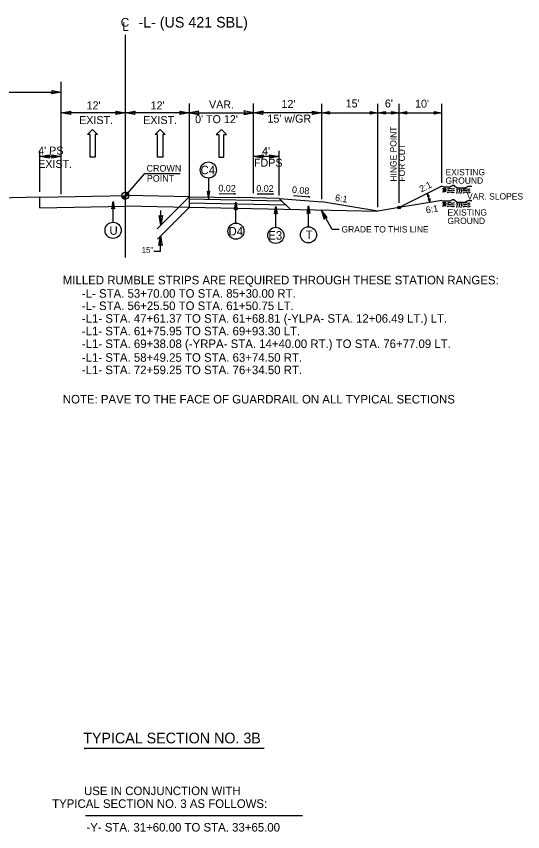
# Model space of a CAD drawing. Extents: x 573813 to 575363, y -54752 to -53123.
# Drawn here: x 574446.6 to 574554.5, y -53538.7 to -53364.9 of the extents above; entities that cross this region are included whole.
import ezdxf

# ---------------------------------------------------------------- set-up
doc = ezdxf.new("R2010")
doc.units = 0
for name, color, linetype in [('Old_Level_1', 7, 'Continuous'), ('Old_Level_11', 7, 'Continuous'), ('Old_Level_2', 7, 'Continuous'), ('Old_Level_3', 7, 'Continuous'), ('Old_Level_4', 7, 'Continuous'), ('Prop Pavement Schedule Description CELL', 7, 'Continuous'), ('Typical Grade Point Symbol CELL', 7, 'Continuous'), ('Typical ID Circle CELL', 7, 'Continuous'), ('Typical Pavement Slope CELL', 7, 'Continuous'), ('Typical Terminator CELL', 7, 'Continuous'), ('Typical Text ID Circle CELL', 7, 'Continuous')]:
    doc.layers.add(name, color=color, linetype=linetype)

msp = doc.modelspace()

# ---------------------------------------------------------------- linework, layer by layer
at = {"layer": 'Old_Level_1'}
for p, q in [((574493, -53402.58), (574493.38, -53402.77)), ((574537.31, -53401.09), (574528.21, -53405.64)), ((574451.69, -53403.42), (574442.59, -53403.61)), ((574451.69, -53403.42), (574470.39, -53403.1)), ((574451.69, -53405.68), (574451.69, -53403.42)), ((574483.52, -53403.32), (574470.39, -53403.1)), ((574483.52, -53405.56), (574483.52, -53403.29)), ((574483.52, -53403.32), (574494.22, -53403.51)), ((574503.26, -53404.29), (574483.52, -53403.88)), ((574493.38, -53402.77), (574489.87, -53402.7)), ((574502.65, -53403.68), (574494.22, -53403.51)), ((574501.46, -53402.82), (574497.95, -53402.75)), ((574501.08, -53402.63), (574501.46, -53402.82)), ((574502.65, -53403.68), (574511.75, -53404.41)), ((574502.65, -53403.68), (574504.98, -53406.01)), ((574509.22, -53403.41), (574505.72, -53403.11)), ((574508.85, -53403.2), (574509.22, -53403.41)), ((574537.31, -53404.12), (574528.21, -53405.64)), ((574451.69, -53405.68), (574469.88, -53405.36)), ((574483.49, -53405.6), (574469.88, -53405.36)), ((574483.52, -53404.64), (574504.04, -53405.07)), ((574483.52, -53405.56), (574523.67, -53406.4)), ((574523.67, -53406.4), (574511.75, -53404.41)), ((574528.21, -53405.64), (574523.67, -53406.4))]:
    msp.add_line(p, q, dxfattribs=at)
for points in [[(574537.31, -53401.09), (574538.2, -53401.2), (574538.43, -53401.2), (574538.76, -53401.2), (574538.99, -53401.2), (574539.21, -53401.09), (574539.44, -53400.98), (574539.66, -53400.87), (574539.88, -53400.87), (574540, -53401.09), (574540.22, -53401.2), (574540.44, -53401.32), (574540.67, -53401.43), (574540.89, -53401.43), (574541.12, -53401.43), (574541.34, -53401.43), (574541.56, -53401.43), (574541.79, -53401.43), (574542.01, -53401.43), (574542.24, -53401.43), (574542.46, -53401.32), (574542.69, -53401.2), (574542.91, -53401.09), (574543.25, -53401.09), (574543.47, -53401.09), (574543.69, -53401.09)], [(574537.31, -53404.12), (574538.2, -53404.23), (574538.43, -53404.23), (574538.76, -53404.23), (574538.99, -53404.23), (574539.21, -53404.12), (574539.44, -53404.01), (574539.66, -53403.9), (574539.88, -53403.9), (574540, -53404.12), (574540.22, -53404.23), (574540.44, -53404.35), (574540.67, -53404.46), (574540.89, -53404.46), (574541.12, -53404.46), (574541.34, -53404.46), (574541.56, -53404.46), (574541.79, -53404.46), (574542.01, -53404.46), (574542.24, -53404.46), (574542.46, -53404.35), (574542.69, -53404.23), (574542.91, -53404.12), (574543.25, -53404.12), (574543.47, -53404.12), (574543.69, -53404.12)]]:
    msp.add_lwpolyline(points, dxfattribs=at)
msp.add_circle((574528.21, -53405.64), 0.27, dxfattribs=at)
msp.add_arc((574527.83, -53405.75), 7.04, 9.8122, 26.0666, dxfattribs=at)
at = {"layer": 'Old_Level_11'}
for p, q in [((574456.24, -53401.29), (574456.24, -53378.84)), ((574372.1, -53381.02), (574456.24, -53381.02)), ((574483.52, -53400.65), (574483.53, -53383.48)), ((574497.16, -53402.6), (574497.16, -53383.48)), ((574511.75, -53403.84), (574511.75, -53383.55)), ((574523.69, -53405.57), (574523.69, -53383.55)), ((574528.21, -53404.65), (574528.21, -53383.55)), ((574537.31, -53400.38), (574537.31, -53383.55)), ((574469.88, -53385.43), (574456.24, -53385.43)), ((574483.53, -53385.43), (574469.88, -53385.43)), ((574483.52, -53385.42), (574497.16, -53385.42)), ((574511.75, -53385.42), (574497.16, -53385.42)), ((574511.75, -53385.42), (574522.8, -53385.42)), ((574522.8, -53385.42), (574528.25, -53385.42)), ((574528.25, -53385.42), (574537.35, -53385.42)), ((574456.24, -53402.76), (574456.24, -53387.72)), ((574451.69, -53402.3), (574451.69, -53393.57)), ((574483.52, -53403.21), (574483.52, -53392.7)), ((574483.52, -53402.87), (574483.52, -53392.81)), ((574502.67, -53403.05), (574502.67, -53393.57)), ((574456.24, -53394.76), (574451.69, -53394.76)), ((574502.67, -53394.74), (574497.16, -53394.74)), ((574456.24, -53402.76), (574456.24, -53396.25)), ((574469.88, -53403.11), (574474.05, -53398.38)), ((574474.05, -53398.38), (574481.55, -53398.38)), ((574483.52, -53403.29), (574476.65, -53410.16)), ((574483.52, -53405.56), (574476.72, -53412.37)), ((574477.42, -53409.37), (574477.42, -53406.29)), ((574513.93, -53410.33), (574511.6, -53406.14)), ((574515.44, -53410.33), (574513.93, -53410.33)), ((574477.38, -53414.91), (574477.38, -53411.7)), ((574475.92, -53414.91), (574477.38, -53414.91)), ((574499.46, -53520.94), (574461.09, -53520.94)), ((574461.39, -53535.24), (574507.63, -53535.24))]:
    msp.add_line(p, q, dxfattribs=at)
for points in [[(574454.19, -53380.67), (574456.24, -53381.02), (574454.18, -53381.39), (574454.44, -53381.02)], [(574458.28, -53385.78), (574456.24, -53385.43), (574458.3, -53385.07), (574458.03, -53385.43)], [(574467.83, -53385.08), (574469.88, -53385.43), (574467.82, -53385.8), (574468.08, -53385.43)], [(574471.93, -53385.78), (574469.88, -53385.43), (574471.94, -53385.07), (574471.68, -53385.43)], [(574481.48, -53385.08), (574483.53, -53385.43), (574481.47, -53385.8), (574481.73, -53385.43)], [(574485.57, -53385.07), (574483.52, -53385.42), (574485.58, -53385.78), (574485.32, -53385.42)], [(574495.11, -53385.77), (574497.16, -53385.42), (574495.1, -53385.05), (574495.36, -53385.42)], [(574499.2, -53385.77), (574497.16, -53385.42), (574499.21, -53385.05), (574498.95, -53385.42)], [(574509.7, -53385.07), (574511.75, -53385.42), (574509.69, -53385.78), (574509.95, -53385.42)], [(574513.39, -53385.7), (574511.75, -53385.42), (574513.39, -53385.13), (574513.19, -53385.42)], [(574522.05, -53385.14), (574523.69, -53385.42), (574522.05, -53385.71), (574522.25, -53385.42)], [(574525.33, -53385.7), (574523.69, -53385.42), (574525.34, -53385.13), (574525.13, -53385.42)], [(574526.57, -53385.14), (574528.21, -53385.42), (574526.56, -53385.71), (574526.77, -53385.42)], [(574529.85, -53385.7), (574528.21, -53385.42), (574529.86, -53385.13), (574529.65, -53385.42)], [(574535.67, -53385.14), (574537.31, -53385.42), (574535.66, -53385.71), (574535.87, -53385.42)], [(574453.74, -53395.11), (574451.69, -53394.76), (574453.75, -53394.4), (574453.49, -53394.76)], [(574454.19, -53394.41), (574456.24, -53394.76), (574454.18, -53395.12), (574454.44, -53394.76)], [(574499.2, -53395.1), (574497.16, -53394.74), (574499.21, -53394.38), (574498.95, -53394.74)], [(574500.62, -53394.39), (574502.67, -53394.74), (574500.61, -53395.11), (574500.87, -53394.74)], [(574534.38, -53403.45), (574534.15, -53402.65), (574534.64, -53403.33), (574534.46, -53403.3)], [(574534.76, -53403.72), (574534.76, -53404.55), (574534.48, -53403.76), (574534.64, -53403.84)], [(574477.77, -53407.32), (574477.42, -53409.37), (574477.06, -53407.31), (574477.42, -53407.57)], [(574512.89, -53407.76), (574511.6, -53406.14), (574512.27, -53408.12), (574512.47, -53407.72)], [(574477.03, -53413.75), (574477.38, -53411.7), (574477.75, -53413.76), (574477.38, -53413.5)]]:
    msp.add_lwpolyline(points, close=True, dxfattribs=at)
at = {"layer": 'Old_Level_2'}
for p, q in [((574469.88, -53385.94), (574469.88, -53368.79)), ((574469.88, -53416.28), (574469.88, -53385.94))]:
    msp.add_line(p, q, dxfattribs=at)
for points in [[(574537.46, -53401.41), (574537.62, -53401.86), (574537.45, -53402.46)], [(574537.46, -53401.41), (574537.62, -53401.86), (574537.45, -53402.46)], [(574537.73, -53401.36), (574537.88, -53401.81), (574537.71, -53402.41)], [(574537.73, -53401.36), (574537.88, -53401.81), (574537.71, -53402.41)], [(574538.01, -53401.33), (574538.17, -53401.78), (574538, -53402.38)], [(574538.01, -53401.33), (574538.17, -53401.78), (574538, -53402.38)], [(574538.45, -53402.45), (574539, -53402.29), (574539.58, -53402.44), (574539.99, -53402.35)], [(574538.45, -53402.45), (574539, -53402.29), (574539.58, -53402.44), (574539.99, -53402.35)], [(574538.49, -53401.68), (574539.04, -53401.53), (574539.62, -53401.67), (574540.03, -53401.58)], [(574538.49, -53401.68), (574539.04, -53401.53), (574539.62, -53401.67), (574540.03, -53401.58)], [(574538.49, -53402.06), (574539.04, -53401.91), (574539.62, -53402.06), (574540.03, -53401.96)], [(574538.49, -53402.06), (574539.04, -53401.91), (574539.62, -53402.06), (574540.03, -53401.96)], [(574540.41, -53401.55), (574540.56, -53402.01), (574540.4, -53402.61)], [(574540.41, -53401.55), (574540.56, -53402.01), (574540.4, -53402.61)], [(574540.88, -53401.59), (574541.04, -53402.04), (574540.87, -53402.64)], [(574540.88, -53401.59), (574541.04, -53402.04), (574540.87, -53402.64)], [(574541.33, -53401.63), (574541.48, -53402.08), (574541.31, -53402.68)], [(574541.33, -53401.63), (574541.48, -53402.08), (574541.31, -53402.68)], [(574541.78, -53401.74), (574542.33, -53401.58), (574542.9, -53401.73), (574543.32, -53401.63)], [(574541.78, -53401.74), (574542.33, -53401.58), (574542.9, -53401.73), (574543.32, -53401.63)], [(574541.79, -53402.08), (574542.34, -53401.92), (574542.92, -53402.07), (574543.33, -53401.98)], [(574541.79, -53402.08), (574542.34, -53401.92), (574542.92, -53402.07), (574543.33, -53401.98)], [(574541.85, -53402.48), (574542.4, -53402.32), (574542.97, -53402.47), (574543.39, -53402.37)], [(574541.85, -53402.48), (574542.4, -53402.32), (574542.97, -53402.47), (574543.39, -53402.37)], [(574538.01, -53404.33), (574538.17, -53404.78), (574538, -53405.38)], [(574538.01, -53404.33), (574538.17, -53404.78), (574538, -53405.38)], [(574537.46, -53404.41), (574537.62, -53404.86), (574537.45, -53405.46)], [(574537.46, -53404.41), (574537.62, -53404.86), (574537.45, -53405.46)], [(574537.73, -53404.36), (574537.88, -53404.81), (574537.71, -53405.41)], [(574537.73, -53404.36), (574537.88, -53404.81), (574537.71, -53405.41)], [(574538.45, -53405.44), (574539, -53405.29), (574539.58, -53405.43), (574539.99, -53405.34)], [(574538.45, -53405.44), (574539, -53405.29), (574539.58, -53405.43), (574539.99, -53405.34)], [(574538.49, -53404.68), (574539.04, -53404.52), (574539.62, -53404.67), (574540.03, -53404.58)], [(574538.49, -53404.68), (574539.04, -53404.52), (574539.62, -53404.67), (574540.03, -53404.58)], [(574538.49, -53405.06), (574539.04, -53404.91), (574539.62, -53405.05), (574540.03, -53404.96)], [(574538.49, -53405.06), (574539.04, -53404.91), (574539.62, -53405.05), (574540.03, -53404.96)], [(574540.41, -53404.55), (574540.56, -53405), (574540.4, -53405.6)], [(574540.41, -53404.55), (574540.56, -53405), (574540.4, -53405.6)], [(574540.88, -53404.59), (574541.04, -53405.04), (574540.87, -53405.64)], [(574540.88, -53404.59), (574541.04, -53405.04), (574540.87, -53405.64)], [(574541.33, -53404.63), (574541.48, -53405.08), (574541.31, -53405.68)], [(574541.33, -53404.63), (574541.48, -53405.08), (574541.31, -53405.68)], [(574541.78, -53404.73), (574542.33, -53404.58), (574542.9, -53404.72), (574543.32, -53404.63)], [(574541.78, -53404.73), (574542.33, -53404.58), (574542.9, -53404.72), (574543.32, -53404.63)], [(574541.79, -53405.07), (574542.34, -53404.92), (574542.92, -53405.07), (574543.33, -53404.97)], [(574541.79, -53405.07), (574542.34, -53404.92), (574542.92, -53405.07), (574543.33, -53404.97)], [(574541.85, -53405.47), (574542.4, -53405.32), (574542.97, -53405.46), (574543.39, -53405.37)], [(574541.85, -53405.47), (574542.4, -53405.32), (574542.97, -53405.46), (574543.39, -53405.37)]]:
    msp.add_spline(points, degree=3, dxfattribs=at)
at = {"layer": 'Old_Level_4'}
for p, q in [((574461.83, -53390.1), (574462.89, -53389.03)), ((574462.35, -53390.1), (574461.83, -53390.1)), ((574462.35, -53394.88), (574462.35, -53390.1)), ((574462.89, -53389.03), (574463.98, -53390.1)), ((574463.98, -53390.1), (574463.47, -53390.1)), ((574463.47, -53390.1), (574463.47, -53394.88)), ((574476.24, -53390.1), (574477.3, -53389.03)), ((574476.75, -53390.1), (574476.24, -53390.1)), ((574476.75, -53394.88), (574476.75, -53390.1)), ((574477.3, -53389.03), (574478.39, -53390.1)), ((574478.39, -53390.1), (574477.88, -53390.1)), ((574477.88, -53390.1), (574477.88, -53394.88)), ((574490.35, -53389.03), (574489.25, -53390.1)), ((574489.25, -53390.1), (574489.77, -53390.1)), ((574489.77, -53390.1), (574489.77, -53394.88)), ((574491.4, -53390.1), (574490.35, -53389.03)), ((574490.89, -53394.88), (574490.89, -53390.1)), ((574490.89, -53390.1), (574491.4, -53390.1)), ((574463.47, -53394.88), (574462.35, -53394.88)), ((574477.88, -53394.88), (574476.75, -53394.88)), ((574489.77, -53394.88), (574490.89, -53394.88))]:
    msp.add_line(p, q, dxfattribs=at)
at = {"layer": 'Typical Grade Point Symbol CELL'}
for p, q in [((574469.88, -53403.11), (574469.88, -53402.34)), ((574469.12, -53403.11), (574469.88, -53403.11)), ((574470.64, -53403.11), (574469.88, -53403.11)), ((574469.88, -53403.87), (574469.88, -53403.11)), ((574469.88, -53403.11), (574469.88, -53403.87))]:
    msp.add_line(p, q, dxfattribs=at)
for points in [[(574469.89, -53402.34), (574469.89, -53402.34), (574469.89, -53403.11)], [(574469.9, -53402.34), (574469.9, -53403.11)], [(574469.92, -53402.35), (574469.92, -53403.11)], [(574469.93, -53402.35), (574469.93, -53403.11)], [(574469.95, -53402.35), (574469.95, -53403.11)], [(574469.96, -53402.35), (574469.96, -53403.11)], [(574469.98, -53402.35), (574469.98, -53403.11)], [(574469.99, -53402.35), (574469.99, -53403.11)], [(574470.01, -53402.35), (574470.01, -53403.11)], [(574470.03, -53402.36), (574470.03, -53403.11)], [(574470.04, -53402.36), (574470.04, -53403.11)], [(574470.06, -53402.36), (574470.06, -53403.11)], [(574470.07, -53402.37), (574470.07, -53403.11)], [(574470.09, -53402.37), (574470.09, -53403.11)], [(574470.1, -53402.38), (574470.1, -53403.11)], [(574470.12, -53402.38), (574470.12, -53403.11)], [(574470.13, -53402.39), (574470.13, -53403.11)], [(574470.15, -53402.39), (574470.15, -53403.11)], [(574470.16, -53402.4), (574470.16, -53403.11)], [(574470.18, -53402.41), (574470.18, -53403.11)], [(574470.19, -53402.41), (574470.19, -53403.11)], [(574470.21, -53402.42), (574470.21, -53403.11)], [(574470.22, -53402.43), (574470.22, -53403.11)], [(574470.24, -53402.43), (574470.24, -53403.11)], [(574470.25, -53402.44), (574470.25, -53403.11)], [(574470.27, -53402.45), (574470.27, -53403.11)], [(574470.28, -53402.46), (574470.28, -53403.11)], [(574470.3, -53402.47), (574470.3, -53403.11)], [(574470.32, -53402.48), (574470.32, -53403.11)], [(574470.33, -53402.49), (574470.33, -53403.11)], [(574470.35, -53402.5), (574470.35, -53403.11)], [(574470.36, -53402.51), (574470.36, -53403.11)], [(574470.38, -53402.53), (574470.38, -53403.11)], [(574470.39, -53402.54), (574470.39, -53403.11)], [(574470.41, -53402.55), (574470.41, -53403.11)], [(574470.42, -53402.57), (574470.42, -53403.11)], [(574470.44, -53402.59), (574470.44, -53403.11)], [(574470.45, -53402.6), (574470.45, -53403.11)], [(574469.12, -53403.11), (574469.12, -53403.19)], [(574469.14, -53403.11), (574469.14, -53403.28)], [(574469.15, -53403.11), (574469.15, -53403.33)], [(574469.17, -53403.11), (574469.17, -53403.38)], [(574469.18, -53403.11), (574469.18, -53403.42)], [(574469.2, -53403.11), (574469.2, -53403.45)], [(574469.21, -53403.11), (574469.21, -53403.48)], [(574469.23, -53403.11), (574469.23, -53403.5)], [(574469.24, -53403.11), (574469.24, -53403.53)], [(574469.26, -53403.11), (574469.26, -53403.55)], [(574469.27, -53403.11), (574469.27, -53403.57)], [(574469.29, -53403.11), (574469.29, -53403.59)], [(574469.3, -53403.11), (574469.3, -53403.61)], [(574469.32, -53403.11), (574469.32, -53403.63)], [(574469.33, -53403.11), (574469.33, -53403.64)], [(574469.35, -53403.11), (574469.35, -53403.66)], [(574469.37, -53403.11), (574469.37, -53403.67)], [(574469.38, -53403.11), (574469.38, -53403.68)], [(574469.4, -53403.11), (574469.4, -53403.7)], [(574469.41, -53403.11), (574469.41, -53403.71)], [(574469.43, -53403.11), (574469.43, -53403.72)], [(574469.44, -53403.11), (574469.44, -53403.73)], [(574469.46, -53403.11), (574469.46, -53403.74)], [(574469.47, -53403.11), (574469.47, -53403.75)], [(574469.49, -53403.11), (574469.49, -53403.76)], [(574469.5, -53403.11), (574469.5, -53403.77)], [(574469.52, -53403.11), (574469.52, -53403.78)], [(574469.53, -53403.11), (574469.53, -53403.79)], [(574469.55, -53403.11), (574469.55, -53403.79)], [(574469.56, -53403.11), (574469.56, -53403.8)], [(574469.58, -53403.11), (574469.58, -53403.81)], [(574469.59, -53403.11), (574469.59, -53403.82)], [(574469.61, -53403.11), (574469.61, -53403.82)], [(574469.62, -53403.11), (574469.62, -53403.83)], [(574469.64, -53403.11), (574469.64, -53403.83)], [(574469.66, -53403.11), (574469.66, -53403.84)], [(574469.67, -53403.11), (574469.67, -53403.84)], [(574469.69, -53403.11), (574469.69, -53403.85)], [(574469.7, -53403.11), (574469.7, -53403.85)], [(574469.72, -53403.11), (574469.72, -53403.85)], [(574469.73, -53403.11), (574469.73, -53403.86)], [(574469.75, -53403.11), (574469.75, -53403.86)], [(574469.76, -53403.11), (574469.76, -53403.86)], [(574469.78, -53403.11), (574469.78, -53403.86)], [(574469.79, -53403.11), (574469.79, -53403.87)], [(574469.81, -53403.11), (574469.81, -53403.87)], [(574469.82, -53403.11), (574469.82, -53403.87)], [(574469.84, -53403.11), (574469.84, -53403.87)], [(574469.85, -53403.11), (574469.85, -53403.87)], [(574469.87, -53403.11), (574469.87, -53403.87), (574469.87, -53403.87)], [(574470.47, -53402.62), (574470.47, -53403.11)], [(574470.48, -53402.64), (574470.48, -53403.11)], [(574470.5, -53402.66), (574470.5, -53403.11)], [(574470.51, -53402.68), (574470.51, -53403.11)], [(574470.53, -53402.71), (574470.53, -53403.11)], [(574470.54, -53402.73), (574470.54, -53403.11)], [(574470.56, -53402.76), (574470.56, -53403.11)], [(574470.57, -53402.79), (574470.57, -53403.11)], [(574470.59, -53402.83), (574470.59, -53403.11)], [(574470.61, -53402.87), (574470.61, -53403.11)], [(574470.62, -53402.92), (574470.62, -53403.11)], [(574470.64, -53403), (574470.64, -53403.11)]]:
    msp.add_lwpolyline(points, dxfattribs=at)
msp.add_circle((574469.88, -53403.11), 0.763, dxfattribs=at)
for start, end in [(359.9905, 89.9905), (179.9905, 269.9905)]:
    msp.add_arc((574469.88, -53403.11), 0.763, start, end, dxfattribs=at)
at = {"layer": 'Typical ID Circle CELL'}
for p, q in [((574487.57, -53399.36), (574487.57, -53403.79)), ((574467.27, -53408.77), (574467.27, -53404.33)), ((574493.44, -53408.96), (574493.44, -53404.52)), ((574501.93, -53409.85), (574501.93, -53405.41)), ((574508.89, -53409.74), (574508.89, -53405.3))]:
    msp.add_line(p, q, dxfattribs=at)
for centre in [(574487.57, -53397.64), (574467.27, -53410.49), (574493.44, -53410.67), (574501.93, -53411.57), (574508.89, -53411.45)]:
    msp.add_circle(centre, 1.72, dxfattribs=at)
at = {"layer": 'Typical Pavement Slope CELL'}
msp.add_line((574461.09, -53520.94), (574461.31, -53520.94), dxfattribs=at)
at = {"layer": 'Typical Terminator CELL'}
for points in [[(574487.3, -53402.2), (574487.57, -53403.79), (574487.85, -53402.2), (574487.57, -53402.4)], [(574467, -53405.92), (574467.27, -53404.33), (574467.56, -53405.93), (574467.27, -53405.73)], [(574493.16, -53406.11), (574493.44, -53404.52), (574493.72, -53406.12), (574493.44, -53405.91)], [(574501.66, -53407), (574501.93, -53405.41), (574502.21, -53407.01), (574501.93, -53406.81)], [(574508.62, -53406.89), (574508.89, -53405.3), (574509.18, -53406.9), (574508.89, -53406.7)]]:
    msp.add_lwpolyline(points, close=True, dxfattribs=at)

# ---------------------------------------------------------------- texts
at = {"layer": 'Old_Level_1'}
for s, height, rotation, p in [("12'", 1.705, 0.0002, (574461.63, -53384.71)), ("12'", 1.705, 0.0002, (574475.27, -53384.71)), ('VAR.', 1.705, 359.9998, (574487.71, -53384.52)), ('EXIST.', 1.705, 0.0002, (574460.04, -53387.84)), ('EXIST.', 1.705, 0.0002, (574473.69, -53387.84)), ("0' TO 12'", 1.705, 359.9998, (574484.74, -53387.65)), ('HINGE POINT', 1.3498, 90, (574527.66, -53400.11)), ('FOR CUT ', 1.35, 90, (574529.47, -53400.11)), ('EXISTING', 1.35, 360, (574538.09, -53398.76)), ('0.02', 1.421, 359.3937, (574489.7, -53402.21)), ('0.02', 1.421, 359.3937, (574497.78, -53402.26)), ('2:1', 1.421, 26.565, (574532.95, -53402.42)), ('GROUND', 1.35, 360, (574538.09, -53400.57)), ('0.08', 1.421, 355.3327, (574505.34, -53402.52)), ('VAR. SLOPES', 1.3502, 360, (574542.68, -53403.93)), ('6:1', 1.421, 350.5376, (574514.49, -53404.18)), ('6:1', 1.421, 9.4634, (574534.02, -53406.89)), ('EXISTING', 1.35, 360, (574538.5, -53407.35)), ('GROUND', 1.35, 360, (574538.5, -53409.16)), ('MILLED RUMBLE STRIPS ARE REQUIRED THROUGH THESE STATION RANGES:', 1.8192, 360, (574456.56, -53422.01)), ('-L- STA. 53+70.00 TO STA. 85+30.00 RT.', 1.8192, 0, (574460.61, -53424.86)), ('-L- STA. 56+25.50 TO STA. 61+50.75 LT.', 1.8192, 0, (574460.61, -53427.49)), ('-L1- STA. 47+61.37 TO STA. 61+68.81 (-YLPA- STA. 12+06.49 LT.) LT.', 1.8192, 0, (574460.61, -53430.19)), ('-L1- STA. 61+75.95 TO STA. 69+93.30 LT.', 1.8192, 0, (574460.61, -53432.88)), ('-L1- STA. 69+38.08 (-YRPA- STA. 14+40.00 RT.) TO STA. 76+77.09 LT.', 1.8192, 0, (574460.61, -53435.58)), ('-L1- STA. 58+49.25 TO STA. 63+74.50 RT.', 1.8192, 0, (574460.61, -53438.51)), ('-L1- STA. 72+59.25 TO STA. 76+34.50 RT.', 1.8192, 0, (574460.61, -53441.15)), ('NOTE: PAVE TO THE FACE OF GUARDRAIL ON ALL TYPICAL SECTIONS', 1.8192, 360, (574456.56, -53447.4)), ('TYPICAL SECTION NO. 3B', 2.2739, 0, (574460.9, -53519.85)), ('USE IN CONJUNCTION WITH ', 1.8192, 360, (574461.07, -53530.88)), ('      TYPICAL SECTION NO. 3 AS FOLLOWS:', 1.8192, 360, (574450.23, -53533.61)), ('-Y- STA. 31+60.00 TO STA. 33+65.00', 1.8192, 0, (574461.59, -53538.65))]:
    msp.add_text(s, height=height, rotation=rotation, dxfattribs=at).set_placement(p)
at = {"layer": 'Old_Level_11'}
for s, height, rotation, p in [("12'", 1.705, 0.0002, (574503.15, -53384.42)), ("15'", 1.705, 360, (574516.83, -53384.31)), ("6'", 1.705, 360, (574525.18, -53384.31)), ("10'", 1.705, 360, (574531.61, -53384.35)), ("15' w/GR", 1.705, 0.0002, (574500.16, -53387.54)), ("4' PS", 1.705, 359.9982, (574451.31, -53394.35)), ("4'", 1.705, 359.9982, (574499.01, -53394.46)), ('EXIST.', 1.705, 359.9982, (574451.31, -53397.19)), ('FDPS', 1.705, 0.0018, (574497.29, -53396.93)), ('GRADE TO THIS LINE', 1.3502, 360, (574515.94, -53410.95))]:
    msp.add_text(s, height=height, rotation=rotation, dxfattribs=at).set_placement(p)
at = {"layer": 'Old_Level_2'}
for s, rotation, p in [('C', 359.9999, (574468.9, -53367.09)), ('L', 359.9468, (574469.22, -53367.97))]:
    msp.add_text(s, height=1.87, rotation=rotation, dxfattribs=at).set_placement(p)
at = {"layer": 'Old_Level_3'}
for s, height, p in [('-L- (US 421 SBL)', 2.2739, (574472.66, -53367.27)), ('CROWN', 1.421, (574474.41, -53397.98)), ('POINT', 1.421, (574474.46, -53400.13))]:
    msp.add_text(s, height=height, rotation=359.9982, dxfattribs=at).set_placement(p)
at = {"layer": 'Prop Pavement Schedule Description CELL'}
for s, p in [('C4', (574485.9, -53398.54)), ('U ', (574466.5, -53411.44)), ('D4', (574491.86, -53411.59)), ('E3', (574500.33, -53412.48))]:
    msp.add_text(s, height=1.819, dxfattribs=at).set_placement(p)
msp.add_text('T', height=1.82, rotation=360, dxfattribs=at).set_placement((574508.29, -53412.36))
at = {"layer": 'Typical Text ID Circle CELL'}
msp.add_text('15"', height=1.23, dxfattribs=at).set_placement((574473.36, -53415.28))

doc.saveas('drawing.dxf')
